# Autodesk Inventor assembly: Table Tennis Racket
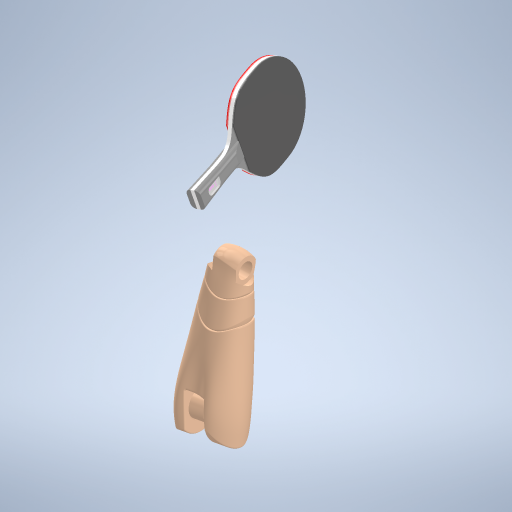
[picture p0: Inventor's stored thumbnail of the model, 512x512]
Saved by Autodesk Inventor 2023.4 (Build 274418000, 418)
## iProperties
Created: 2019-07
Part Number: Table Tennis Racket
Material: Générique
Document SubType Name: Modeling
Designer: bruno
Density: 1 g/cm^3
Appearance: Par défaut
Author: bruno
Sending System: SolidWorks 2016
Last Author: prince19947
Last Saved: 2019-07-27
Created: 2019-10
Part Number: Hand Full-ping-pong
Document SubType Name: Assembly
Designer: yello
Author: yello
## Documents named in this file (5)
- **C:\Users\bruno\Documents\1-Cours-2025-26\1STI2D\ETLV\Diversité et inclusion\Hand Full-ping-pong.iam*LocalDocs*xAaaaqfbaAaaaaaaaAaaaqcxxUa*Table Tennis Racket.ipt
- C:\Users\bruno\Documents\1-Cours-2025-26\1STI2D\ETLV\Diversité et inclusion\Hand Full-ping-pong.iam
- C:\Users\bruno\Documents\1-Cours-2025-26\1STI2D\ETLV\Diversité et inclusion\Prototype 2 (Realistic Hand)\Wrist Rotation.ipt
- C:\Users\bruno\Documents\1-Cours-2025-26\1STI2D\ETLV\Diversité et inclusion\Prototype 2 (Realistic Hand)\Arm to Wrist Connection.ipt
- C:\Users\bruno\Documents\1-Cours-2025-26\1STI2D\ETLV\Diversité et inclusion\Prototype 2 (Realistic Hand)\Arm.ipt
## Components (4 placed, 4 different names)
1. Wrist Rotation:1 — Mate:1, Mate:2, Mate:4
2. Arm to Wrist Connection:1 — Mate:1, Mate:2, Mate:3
3. Arm:1 — Mate:3, Mate:4
4. Table Tennis Racket:1
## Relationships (4: Mate 4)
- Mate:1: Wrist Rotation:1 ↔ Arm to Wrist Connection:1
- Mate:2: Wrist Rotation:1 ↔ Arm to Wrist Connection:1
- Mate:3: Arm to Wrist Connection:1 ↔ Arm:1
- Mate:4: Wrist Rotation:1 ↔ Arm:1
